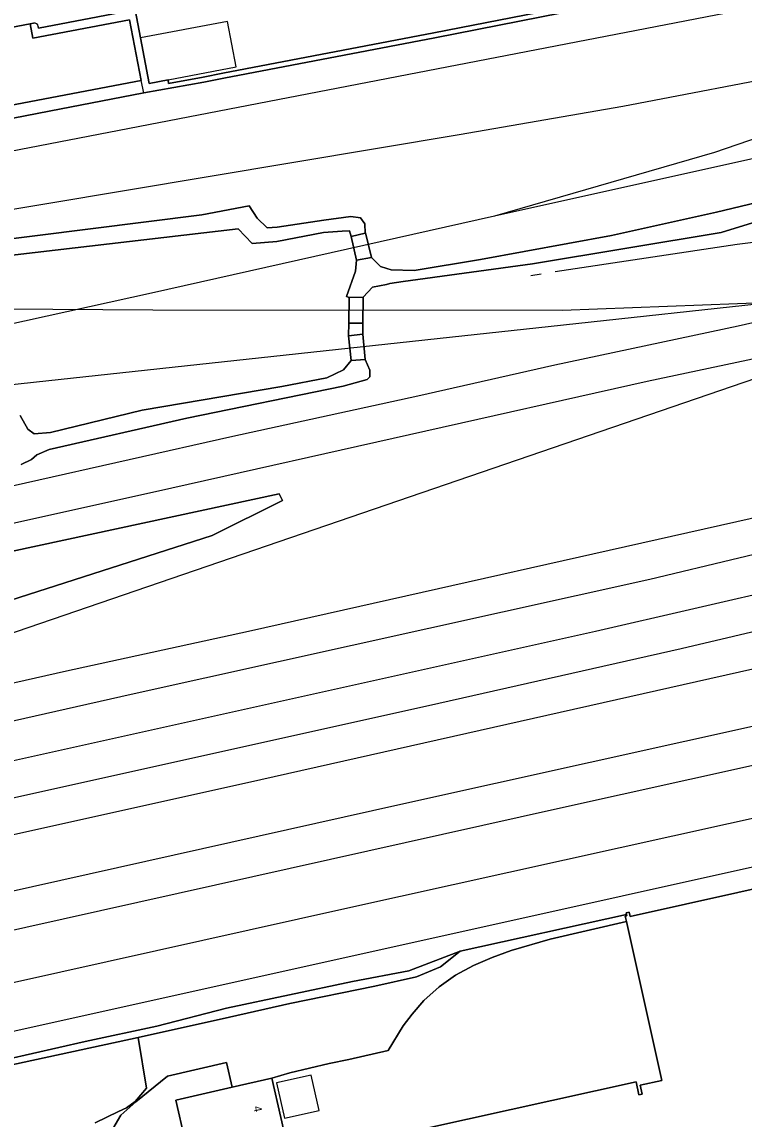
# Model space of a CAD drawing. Extents: x 161477 to 163040, y 383680 to 384871.
# Drawn here: x 161808.8 to 161899, y 383769.2 to 383906.2 of the extents above; entities that cross this region are included whole.
import ezdxf

# ---------------------------------------------------------------- set-up
doc = ezdxf.new("R2010")
doc.units = 0
for name, color, linetype in [('IMGEO_Erf', 7, 'Continuous'), ('IMGEO_Grasland_overig', 7, 'Continuous'), ('IMGEO_Hek', 7, 'Continuous'), ('IMGEO_Overkapping', 7, 'Continuous'), ('IMGEO_Overweg_gesloten', 7, 'Continuous'), ('IMGEO_Pand', 7, 'Continuous'), ('IMGEO_Pand_nummerreeks', 7, 'Continuous'), ('IMGEO_Rijbaan_lokaal_open', 7, 'Continuous'), ('IMGEO_Spoor', 7, 'Continuous'), ('IMGEO_Spoorbaan_halfverhard', 7, 'Continuous'), ('IMGEO_Terreindeel_halfverhard', 7, 'Continuous'), ('IMGEO_Terreindeel_onvherhard', 7, 'Continuous'), ('IMGEO_Terreindeel_open', 7, 'Continuous')]:
    doc.layers.add(name, color=color, linetype=linetype)

msp = doc.modelspace()

# ---------------------------------------------------------------- linework, layer by layer
at = {"layer": 'IMGEO_Erf'}
for points in [[(161822.96, 383907.74), (161823.62, 383904.23), (161824.71, 383898.53), (161827.07, 383898.98), (161827.15, 383898.54), (161831.44, 383899.32), (161833.92, 383899.83), (161860.26, 383904.85), (161881.39, 383909.02)], [(161859.41, 383768), (161885.51, 383773.82), (161885.88, 383772.17), (161886.3, 383772.28), (161886.05, 383773.38), (161888.73, 383773.98), (161884.31, 383793.82), (161874.8, 383791.64), (161869.92, 383790.22), (161867.53, 383789.35), (161865.2, 383788.32), (161862.98, 383787.12), (161860.91, 383785.68), (161859.02, 383783.95), (161857.57, 383782.27), (161856.45, 383780.78), (161854.57, 383777.72), (161849.65, 383776.6), (161847.21, 383776.09), (161842.27, 383774.91), (161840.05, 383774.26), (161842.3, 383764.42)], [(161830.29, 383761.68), (161828.04, 383771.52), (161835.09, 383773.13), (161834.38, 383776.23), (161826.99, 383774.49), (161823.06, 383771.32), (161821.16, 383769.65), (161819.88, 383767.43)]]:
    msp.add_lwpolyline(points, dxfattribs=at)
at = {"layer": 'IMGEO_Grasland_overig'}
msp.add_lwpolyline([(161819.88, 383767.43), (161821.16, 383769.65), (161823.06, 383771.32), (161826.99, 383774.49), (161834.38, 383776.23), (161835.09, 383773.13), (161840.05, 383774.26), (161842.27, 383774.91), (161847.21, 383776.09), (161849.65, 383776.6), (161854.57, 383777.72), (161856.45, 383780.78), (161857.57, 383782.27), (161859.02, 383783.95), (161860.91, 383785.68), (161862.98, 383787.12), (161865.2, 383788.32), (161867.53, 383789.35), (161869.92, 383790.22), (161874.8, 383791.64), (161884.31, 383793.82), (161884.16, 383794.49), (161884.38, 383794.54), (161884.34, 383794.72), (161863.54, 383790.11), (161861.09, 383788.17), (161858.12, 383786.9), (161852.9, 383785.75), (161842.3, 383783.57), (161834.74, 383781.86), (161823.36, 383779.33), (161824.4, 383773), (161822.96, 383771.36), (161821.9, 383770.54), (161820.9, 383770.09), (161817.97, 383768.66)], dxfattribs=at)
at = {"layer": 'IMGEO_Hek'}
for points in [[(161824.04, 383897.35), (161831.56, 383898.7), (161834.04, 383899.21), (161860.38, 383904.24), (161881.52, 383908.4)], [(161824.04, 383897.35), (161823.72, 383898.9)], [(161722.08, 383878.3), (161733.2, 383880.57), (161733.17, 383880.72), (161759.83, 383885.64), (161762.09, 383884.87), (161764.6, 383885.31), (161764.77, 383885.44), (161765.68, 383886.11), (161770.75, 383887.11), (161771.45, 383886.85), (161771.67, 383886.77), (161778.08, 383888.01), (161780.17, 383888.88), (161785.28, 383889.86), (161792.64, 383891.29), (161800.01, 383892.71), (161812.23, 383895.08), (161824.04, 383897.35)], [(161884.31, 383793.82), (161874.8, 383791.64), (161869.92, 383790.22), (161867.53, 383789.35), (161865.2, 383788.32), (161862.98, 383787.12), (161860.91, 383785.68), (161859.02, 383783.95), (161857.57, 383782.27), (161856.45, 383780.78), (161854.57, 383777.72), (161849.65, 383776.6), (161847.21, 383776.09), (161842.27, 383774.91), (161840.05, 383774.26)], [(161816.91, 383761.39), (161817.54, 383763.03), (161817.93, 383764.04), (161818.46, 383765.25), (161819.88, 383767.43), (161821.16, 383769.65), (161823.06, 383771.32), (161826.99, 383774.49), (161834.38, 383776.23), (161835.05, 383773.27)]]:
    msp.add_lwpolyline(points, dxfattribs=at)
at = {"layer": 'IMGEO_Overkapping'}
for points in [[(161835.59, 383900.6), (161834.51, 383906.29), (161823.62, 383904.23), (161824.71, 383898.53), (161827.07, 383898.98)], [(161845.93, 383770.23), (161844.94, 383774.64), (161840.62, 383773.68), (161841.61, 383769.27)]]:
    msp.add_lwpolyline(points, close=True, dxfattribs=at)
at = {"layer": 'IMGEO_Overweg_gesloten'}
for points in [[(161851.73, 383879.85), (161851.69, 383879.84), (161849.94, 383879.41), (161850.59, 383876.46), (161852.46, 383876.8)], [(161849.68, 383871.8), (161849.63, 383868.6), (161851.41, 383868.59), (161851.46, 383871.84)], [(161851.4, 383867.22), (161849.59, 383867.01), (161849.93, 383863.92), (161851.7, 383864.04)]]:
    msp.add_lwpolyline(points, close=True, dxfattribs=at)
at = {"layer": 'IMGEO_Pand'}
for points in [[(161804.12, 383904.89), (161784.5, 383901.16), (161786.28, 383891.79), (161823.72, 383898.9), (161822.28, 383906.49), (161810.18, 383904.2), (161809.85, 383905.98)], [(161828.04, 383771.52), (161830.29, 383761.68), (161842.3, 383764.42), (161840.05, 383774.26), (161835.09, 383773.13)]]:
    msp.add_lwpolyline(points, close=True, dxfattribs=at)
msp.add_lwpolyline([(162088.04, 383839.79), (162000, 383820.13), (161884.78, 383794.45), (161884.66, 383795.01), (161884.29, 383794.93), (161884.34, 383794.72), (161884.38, 383794.54), (161884.16, 383794.49), (161884.31, 383793.82), (161888.73, 383773.98), (161886.05, 383773.38), (161886.3, 383772.28), (161885.88, 383772.17), (161885.51, 383773.82), (161859.41, 383768), (161862.46, 383754.35), (161888.64, 383760.19), (161888.12, 383762.5), (161887.37, 383765.86), (161890.33, 383766.52), (161890.45, 383765.98), (162000, 383790.34), (162126.91, 383818.18)], dxfattribs=at)
at = {"layer": 'IMGEO_Rijbaan_lokaal_open'}
for points in [[(161810.87, 383905.66), (161810.91, 383905.45), (161822.03, 383907.56)], [(161804.12, 383904.89), (161809.85, 383905.98), (161810.29, 383906.06)]]:
    msp.add_lwpolyline(points, dxfattribs=at)
msp.add_arc((161810.38, 383905.57), 0.501, 10.7958, 100.746, dxfattribs=at)
at = {"layer": 'IMGEO_Spoor'}
for points in [[(162082.22, 383940.62), (162067.16, 383939.08), (162060.65, 383938.31), (162050.14, 383936.84), (162039.55, 383934.98), (161761.26, 383881.1), (161737.23, 383876.55), (161717.53, 383872.76)], [(162111.79, 383936.09), (161895.74, 383888.14)], [(161750.33, 383784.82), (161856.15, 383808.49), (162010.58, 383842.76), (162025.33, 383846.04), (162038.44, 383849.14), (162081.87, 383858.91), (162203.93, 383886.62), (162328.82, 383914.89), (162363.46, 383922.8), (162370.5, 383924.21), (162377.8, 383925.46), (162384.63, 383926.4), (162393.03, 383927.13), (162402.21, 383927.44), (162408.98, 383927.48)], [(161752.19, 383780.4), (161875.71, 383807.94), (162015.25, 383838.88), (162036.64, 383843.84), (162104.75, 383859.25), (162247.6, 383891.59), (162328.95, 383910.05), (162367.14, 383918.71), (162379.68, 383921.18), (162389.53, 383922.69), (162398.92, 383923.74), (162409, 383924.59)], [(161754.68, 383774.37), (161849.16, 383795.44), (161951.91, 383818.25), (162017.67, 383832.92), (162036.57, 383837.16), (162110.8, 383854.02), (162201.33, 383874.48), (162299.92, 383896.88), (162339.11, 383905.77), (162371.6, 383913.13), (162387.02, 383916.6), (162393.33, 383917.81), (162399.33, 383918.84), (162404.24, 383919.61), (162409.95, 383920.31), (162415.59, 383920.88), (162421.26, 383921.34), (162428.5, 383921.74), (162433.31, 383921.88), (162439.75, 383921.91), (162444.26, 383921.83)], [(161940.49, 383907.28), (161906.48, 383899.97), (161883.87, 383895.64), (161863.41, 383892.09), (161749.22, 383872.99)], [(161940.86, 383905.43), (161929.51, 383901.63), (161895.3, 383889.92)], [(161756.53, 383768.76), (161838.28, 383786.93), (161975.14, 383817.36), (162056.37, 383835.44), (162106.4, 383846.65), (162114.63, 383848.32), (162125.79, 383850.6), (162135.24, 383852.23), (162143.31, 383853.7), (162150.4, 383855), (162159.12, 383856.88), (162165.31, 383858.26), (162254.85, 383878.09), (162292.54, 383886.49), (162314.34, 383891.26), (162320.37, 383892.65), (162328.36, 383894.6), (162337.4, 383896.88)], [(162120.88, 383892.68), (162062.31, 383879.66), (162037.81, 383873.92), (162000.83, 383864.78), (161960.94, 383854.6), (161931.69, 383847.23), (161887.22, 383836.56), (161822.48, 383822.2), (161794.19, 383815.83), (161768.23, 383810.18), (161751.35, 383806.22), (161742.18, 383804.14)], [(161985.42, 383892.7), (161981.38, 383891.97), (161973.49, 383890.38), (161963.54, 383888.55), (161903.11, 383879.05), (161898.15, 383878.4), (161875.4, 383874.99)], [(161895.3, 383889.92), (161867.83, 383881.94)], [(162124.71, 383888.45), (162110.92, 383885.28), (162073.48, 383876.95), (162044.87, 383870.41), (162018.83, 383864.1), (161926.17, 383840.83), (161904.99, 383835.71), (161880.47, 383830.07), (161744.04, 383799.74)], [(162080.4, 383888.27), (162044.96, 383880.31), (162029.1, 383876.52), (161994.28, 383867.84), (161928.36, 383851.12), (161903.85, 383845.06), (161837.13, 383830.06), (161814.39, 383825.1), (161790.23, 383819.66), (161771.31, 383815.49)], [(161895.74, 383888.14), (161867.83, 383881.94)], [(161867.83, 383881.94), (161824.99, 383872.35)], [(161872.38, 383874.53), (161873.67, 383874.73)], [(161824.99, 383872.35), (161806.69, 383868.27)], [(161902.54, 383871.18), (161876.34, 383870.15)], [(161902.54, 383871.18), (161876.44, 383868.34)], [(161825.18, 383870.21), (161806.43, 383870.32)], [(161876.34, 383870.15), (161825.18, 383870.21)], [(161903.4, 383869.39), (161898.27, 383868.21), (161875.37, 383863.33), (161858.28, 383859.48), (161835.18, 383854.42), (161757.45, 383836.94), (161730.85, 383831.03)], [(161876.44, 383868.34), (161792.91, 383859.3)], [(162046.51, 383865.9), (162016.88, 383859.02), (161999.7, 383854.79), (161939.27, 383839.49), (161917.3, 383834.06), (161891.14, 383827.89), (161859.61, 383820.78), (161745.83, 383795.49)], [(161904.37, 383865), (161886.89, 383861.28), (161827.55, 383847.97), (161732.61, 383826.84)], [(162046.94, 383863.93), (162029.39, 383858.02), (162022.57, 383855.93), (161996.39, 383849.13), (161943.61, 383835.84), (161927.99, 383831.97), (161903.41, 383826.11), (161837, 383811.15), (161747.6, 383791.29)], [(161904.91, 383863.21), (161784.26, 383821.87), (161770.68, 383817.3)]]:
    msp.add_lwpolyline(points, dxfattribs=at)
at = {"layer": 'IMGEO_Spoorbaan_halfverhard'}
for points in [[(161881.52, 383908.4), (161860.38, 383904.24), (161834.04, 383899.21), (161831.56, 383898.7), (161824.04, 383897.35), (161812.23, 383895.08), (161800.01, 383892.71)], [(161803.44, 383878.62), (161831.3, 383882.13), (161837.19, 383883.25), (161838.22, 383881.71), (161839.45, 383880.49), (161840.71, 383880.56), (161846.54, 383881.46), (161849.88, 383881.91), (161851.11, 383881.76), (161851.65, 383881.01), (161851.69, 383879.84), (161851.73, 383879.85), (161852.46, 383876.8), (161853.62, 383875.68), (161854.41, 383875.41), (161854.93, 383875.23), (161857.82, 383875.17), (161866.09, 383876.54), (161882.46, 383879.52), (161895.58, 383882.44), (161935.87, 383892.12)], [(161901.16, 383881.46), (161896.14, 383879.9), (161872.57, 383876.01), (161856.45, 383873.8), (161854.77, 383873.55), (161854.35, 383873.42), (161852.6, 383873.07), (161851.46, 383871.84), (161851.41, 383868.59), (161851.4, 383867.22), (161851.7, 383864.04), (161852.26, 383862.71), (161852.28, 383861.89), (161851.96, 383861.56), (161848.93, 383860.7), (161829.43, 383856.71), (161812.22, 383852.78), (161810.68, 383852.13), (161810.03, 383851.56), (161808.72, 383850.93)], [(161808.61, 383857.04), (161809.55, 383855.32), (161810.37, 383854.77), (161812.4, 383854.92), (161823.86, 383857.72), (161841.27, 383860.68), (161846.9, 383861.76), (161848.97, 383862.75), (161849.93, 383863.92), (161849.59, 383867.01), (161849.63, 383868.6), (161849.68, 383871.8), (161849.37, 383871.9), (161850.47, 383875.08), (161850.59, 383876.46), (161849.94, 383879.41), (161849.75, 383880.12), (161848.81, 383880.08), (161846.49, 383879.9), (161840.64, 383878.8), (161837.59, 383878.54), (161835.85, 383880.35), (161803.64, 383876.6)], [(161787.15, 383835.69), (161840.96, 383847.26), (161841.37, 383846.43), (161832.59, 383842.07), (161807.33, 383833.95)], [(161817.97, 383768.66), (161820.9, 383770.09), (161821.9, 383770.54), (161822.96, 383771.36), (161824.4, 383773), (161823.36, 383779.33), (161801.93, 383774.72), (161795.56, 383773.29), (161790.49, 383772.31), (161793.14, 383773.34), (161806.84, 383776.61), (161816.73, 383778.86), (161825.68, 383780.74), (161834.38, 383782.99), (161850.12, 383786.33), (161857.16, 383787.65), (161863.54, 383790.11), (161884.34, 383794.72), (161884.29, 383794.93), (161884.66, 383795.01), (161884.78, 383794.45), (162000, 383820.13)]]:
    msp.add_lwpolyline(points, dxfattribs=at)
at = {"layer": 'IMGEO_Terreindeel_halfverhard'}
for points in [[(161935.87, 383892.12), (161895.58, 383882.44), (161882.46, 383879.52), (161866.09, 383876.54), (161857.82, 383875.17), (161854.93, 383875.23), (161854.41, 383875.41), (161853.62, 383875.68), (161852.46, 383876.8), (161850.59, 383876.46), (161850.47, 383875.08), (161849.37, 383871.9), (161849.68, 383871.8), (161851.46, 383871.84), (161852.6, 383873.07), (161854.35, 383873.42), (161854.77, 383873.55), (161856.45, 383873.8), (161872.57, 383876.01), (161896.14, 383879.9), (161901.16, 383881.46)], [(161803.64, 383876.6), (161835.85, 383880.35), (161837.59, 383878.54), (161840.64, 383878.8), (161846.49, 383879.9), (161848.81, 383880.08), (161849.75, 383880.12), (161849.94, 383879.41), (161851.69, 383879.84), (161851.65, 383881.01), (161851.11, 383881.76), (161849.88, 383881.91), (161846.54, 383881.46), (161840.71, 383880.56), (161839.45, 383880.49), (161838.22, 383881.71), (161837.19, 383883.25), (161831.3, 383882.13), (161803.44, 383878.62)], [(161808.72, 383850.93), (161810.03, 383851.56), (161810.68, 383852.13), (161812.22, 383852.78), (161829.43, 383856.71), (161848.93, 383860.7), (161851.96, 383861.56), (161852.28, 383861.89), (161852.26, 383862.71), (161851.7, 383864.04), (161849.93, 383863.92), (161848.97, 383862.75), (161846.9, 383861.76), (161841.27, 383860.68), (161823.86, 383857.72), (161812.4, 383854.92), (161810.37, 383854.77), (161809.55, 383855.32), (161808.61, 383857.04)]]:
    msp.add_lwpolyline(points, dxfattribs=at)
for points in [[(161851.4, 383867.22), (161851.41, 383868.59), (161849.63, 383868.6), (161849.59, 383867.01)], [(161823.36, 383779.33), (161834.74, 383781.86), (161842.3, 383783.57), (161852.9, 383785.75), (161858.12, 383786.9), (161861.09, 383788.17), (161863.54, 383790.11), (161857.16, 383787.65), (161850.12, 383786.33), (161834.38, 383782.99), (161825.68, 383780.74), (161816.73, 383778.86), (161806.84, 383776.61), (161793.14, 383773.34), (161790.49, 383772.31), (161795.56, 383773.29), (161801.93, 383774.72)]]:
    msp.add_lwpolyline(points, close=True, dxfattribs=at)
at = {"layer": 'IMGEO_Terreindeel_onvherhard'}
msp.add_lwpolyline([(161738.8, 383812.17), (161739.1, 383812.53), (161748.36, 383814.58), (161749.23, 383813.87), (161763.69, 383818.23), (161764.05, 383819.19), (161769.61, 383820.73), (161774.85, 383822.46), (161780, 383824.92), (161804.37, 383833.34), (161807.33, 383833.95), (161832.59, 383842.07), (161841.37, 383846.43), (161840.96, 383847.26), (161787.15, 383835.69), (161752.2, 383827.92), (161741.92, 383825.71), (161734.08, 383823.35)], close=True, dxfattribs=at)
at = {"layer": 'IMGEO_Terreindeel_open'}
for points in [[(161810.29, 383906.06), (161809.85, 383905.98), (161810.18, 383904.2), (161822.28, 383906.49), (161823.72, 383898.9), (161786.28, 383891.79), (161784.5, 383901.16), (161804.12, 383904.89), (161804.05, 383905.32), (161804, 383905.46), (161803.9, 383905.58), (161803.76, 383905.68), (161803.61, 383905.72), (161803.46, 383905.71), (161783.24, 383901.9), (161785.51, 383889.91), (161792.64, 383891.29), (161800.01, 383892.71), (161812.23, 383895.08), (161824.04, 383897.35), (161831.56, 383898.7), (161834.04, 383899.21), (161860.38, 383904.24), (161881.52, 383908.4)], [(161881.39, 383909.02), (161860.26, 383904.85), (161833.92, 383899.83), (161831.44, 383899.32), (161827.15, 383898.54), (161827.07, 383898.98), (161824.71, 383898.53), (161823.62, 383904.23), (161822.96, 383907.74)], [(161822.03, 383907.56), (161810.91, 383905.45), (161810.87, 383905.66)]]:
    msp.add_lwpolyline(points, dxfattribs=at)
msp.add_arc((161810.38, 383905.57), 0.501, 10.7958, 100.746, dxfattribs=at)

# ---------------------------------------------------------------- texts
at = {"layer": 'IMGEO_Pand_nummerreeks'}
msp.add_text('4', height=1, rotation=282.3012, dxfattribs=at).set_placement((161837.72, 383770.68))

doc.saveas('drawing.dxf')
